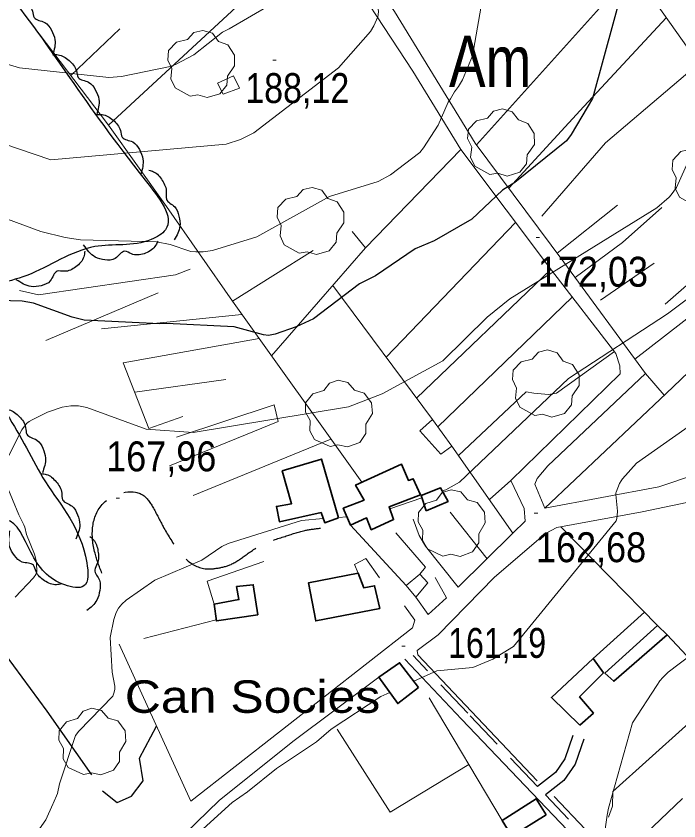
# Model space of a CAD drawing. Extents: x 480269 to 484877, y 4383588 to 4386804.
# Drawn here: x 480900.7 to 481094.5, y 4386070.7 to 4386306.1 of the extents above; entities that cross this region are included whole.
import ezdxf
from ezdxf.enums import TextEntityAlignment as Align

# ---------------------------------------------------------------- set-up
doc = ezdxf.new("R2010")
doc.units = 0
doc.header["$LTSCALE"] = 3.8
doc.linetypes.add('LONG_DASHED', pattern=[7.5, 6, -1.5])
doc.linetypes.add('MEDIUM_DASHED', pattern=[4.5, 3, -1.5])
for name, color, linetype, lineweight in [('25', 7, 'LONG_DASHED', 25), ('27', 7, 'Continuous', 25), ('29', 7, 'Continuous', 13), ('38', 7, 'Continuous', 25), ('47', 7, 'Continuous', 35), ('51', 7, 'Continuous', 13), ('7', 7, 'Continuous', 13), ('8', 7, 'Continuous', 25), ('9', 7, 'Continuous', 13)]:
    doc.layers.add(name, color=color, linetype=linetype, lineweight=lineweight)
doc.layers.add('31', color=7, linetype='Continuous')
doc.layers.add('5', color=7, linetype='Continuous')

msp = doc.modelspace()

# ---------------------------------------------------------------- linework, layer by layer
at = {"layer": '25'}
msp.add_lwpolyline([(480856.34, 4386178.85), (480880.34, 4386147.94), (480897.46, 4386119.43), (480909.61, 4386102.85), (480925.95, 4386079.55), (480930.22, 4386076.16), (480934.45, 4386078), (480937.79, 4386082.41), (480936.79, 4386089.08), (480941.75, 4386098.4)], dxfattribs=at)
at = {"layer": '27'}
for points in [[(480894.74, 4386365.82), (480903.52, 4386357.87), (480897.3, 4386347.37), (480895.04, 4386345.21), (480887.78, 4386337.47), (480888.64, 4386326.66), (480896.85, 4386314.59), (480916.25, 4386288.17), (480938.42, 4386258.12), (480944.36, 4386243.6), (480940.19, 4386240.76), (480923.67, 4386238.66), (480903.77, 4386230.25), (480885.41, 4386225.51), (480878.62, 4386222.15), (480876.15, 4386209.9), (480887.62, 4386200.28), (480897.9, 4386189.68), (480909.25, 4386169.92), (480921.33, 4386146.21), (480920.51, 4386139.43), (480914.92, 4386139.74), (480904.97, 4386149.33), (480897.67, 4386158.69), (480892.34, 4386157.19), (480887.81, 4386154.72)], [(480898.56, 4386312.26), (480900.11, 4386312.28), (480903.33, 4386310.6), (480905.44, 4386307.57), (480905.96, 4386305.65), (480909.02, 4386304.22), (480910.98, 4386301.97), (480912.02, 4386299.19), (480911.4, 4386294.76)], [(480911.39, 4386294.76), (480912.94, 4386294.78), (480916.16, 4386293.11), (480918.28, 4386290.08), (480918.81, 4386288.16), (480921.87, 4386286.74), (480923.83, 4386284.5), (480924.88, 4386281.72), (480924.26, 4386277.29)], [(480924.27, 4386277.29), (480925.82, 4386277.32), (480929.04, 4386275.64), (480931.16, 4386272.62), (480931.68, 4386270.7), (480934.75, 4386269.28), (480936.71, 4386267.04), (480937.76, 4386264.26), (480937.15, 4386259.83)], [(480939.46, 4386261.01), (480940.88, 4386260.57), (480943.41, 4386258.03), (480944.59, 4386254.53), (480944.6, 4386252.55), (480947.05, 4386250.3), (480948.28, 4386247.59), (480948.56, 4386244.64), (480946.91, 4386240.63)], [(480942.06, 4386240.24), (480941.23, 4386238.68), (480938.07, 4386236.6), (480934.38, 4386236.54), (480932.48, 4386237.32), (480929.61, 4386235.22), (480926.66, 4386234.78), (480923.76, 4386235.62), (480920.38, 4386239.24)], [(480920.76, 4386237.34), (480920.47, 4386235.68), (480918.15, 4386232.77), (480914.71, 4386231.45), (480912.68, 4386231.47), (480910.65, 4386228.65), (480908.02, 4386227.25), (480905.03, 4386226.99), (480900.73, 4386228.99)], [(480897.06, 4386191.06), (480898.58, 4386190.93), (480901.61, 4386188.96), (480903.45, 4386185.76), (480903.82, 4386183.8), (480906.72, 4386182.1), (480908.47, 4386179.69), (480909.28, 4386176.84), (480908.34, 4386172.52)], [(480907.99, 4386172.31), (480909.48, 4386172.08), (480912.36, 4386169.92), (480914.01, 4386166.62), (480914.27, 4386164.65), (480917.03, 4386162.76), (480918.63, 4386160.25), (480919.28, 4386157.36), (480918.11, 4386153.12)], [(480914.04, 4386140.06), (480912.47, 4386139.79), (480909, 4386140.96), (480906.49, 4386143.66), (480905.72, 4386145.51), (480902.44, 4386146.44), (480900.18, 4386148.38), (480898.78, 4386151.02), (480898.87, 4386155.58)], [(480922.2, 4386153.9), (480923.29, 4386152.96), (480924.61, 4386149.65), (480924.39, 4386145.96), (480923.67, 4386144.13), (480925.02, 4386141.11), (480925.13, 4386138.14), (480924.29, 4386135.31), (480921.36, 4386132.22)]]:
    msp.add_spline(points, degree=3, dxfattribs=at)
at = {"layer": '29'}
for points in [[(480951.52, 4386282.71), (480947.13, 4386285.14), (480945.91, 4386287.78), (480946.21, 4386290.74), (480945.01, 4386293.24), (480945.25, 4386295.98), (480947.58, 4386298.43), (480950.83, 4386299.2), (480952.63, 4386301.27), (480955.25, 4386301.92), (480958.06, 4386301.07), (480959.85, 4386298.67), (480962.6, 4386297.66), (480964.52, 4386294.67), (480964.54, 4386291.53), (480962.45, 4386288.51), (480962.26, 4386285.84), (480960.26, 4386283.36), (480956.56, 4386282.28), (480953.84, 4386283.1)], [(481039.19, 4386259.75), (481034.8, 4386262.18), (481033.58, 4386264.82), (481033.88, 4386267.78), (481032.68, 4386270.28), (481032.92, 4386273.02), (481035.25, 4386275.47), (481038.5, 4386276.24), (481040.3, 4386278.31), (481042.92, 4386278.96), (481045.73, 4386278.11), (481047.52, 4386275.71), (481050.27, 4386274.7), (481052.19, 4386271.71), (481052.21, 4386268.57), (481050.12, 4386265.55), (481049.93, 4386262.88), (481047.93, 4386260.4), (481044.23, 4386259.32), (481041.51, 4386260.14)], [(481099.01, 4386250.73), (481094.62, 4386253.16), (481093.4, 4386255.8), (481093.7, 4386258.76), (481092.5, 4386261.26), (481092.74, 4386264), (481095.07, 4386266.45), (481098.32, 4386267.22), (481100.12, 4386269.29), (481102.74, 4386269.94), (481105.55, 4386269.09), (481107.34, 4386266.69), (481110.09, 4386265.68), (481112.01, 4386262.69), (481112.03, 4386259.55), (481109.94, 4386256.53), (481109.75, 4386253.86), (481107.75, 4386251.38), (481104.05, 4386250.3), (481101.33, 4386251.12)], [(480983.48, 4386236.8), (480979.09, 4386239.23), (480977.87, 4386241.87), (480978.17, 4386244.83), (480976.97, 4386247.33), (480977.21, 4386250.07), (480979.54, 4386252.52), (480982.79, 4386253.29), (480984.59, 4386255.36), (480987.21, 4386256.01), (480990.02, 4386255.16), (480991.81, 4386252.76), (480994.56, 4386251.75), (480996.48, 4386248.76), (480996.5, 4386245.62), (480994.41, 4386242.6), (480994.22, 4386239.93), (480992.22, 4386237.45), (480988.52, 4386236.37), (480985.8, 4386237.19)], [(481052.3, 4386189.25), (481047.91, 4386191.68), (481046.69, 4386194.32), (481046.99, 4386197.28), (481045.79, 4386199.78), (481046.03, 4386202.52), (481048.36, 4386204.97), (481051.61, 4386205.74), (481053.41, 4386207.81), (481056.03, 4386208.46), (481058.84, 4386207.61), (481060.63, 4386205.21), (481063.38, 4386204.2), (481065.3, 4386201.21), (481065.32, 4386198.07), (481063.23, 4386195.05), (481063.04, 4386192.38), (481061.04, 4386189.9), (481057.34, 4386188.82), (481054.62, 4386189.64)], [(480992.46, 4386180.18), (480987.92, 4386182.3), (480986.51, 4386184.84), (480986.61, 4386187.82), (480985.24, 4386190.23), (480985.28, 4386192.98), (480987.44, 4386195.58), (480990.63, 4386196.58), (480992.28, 4386198.77), (480994.85, 4386199.6), (480997.71, 4386198.95), (480999.66, 4386196.68), (481002.47, 4386195.86), (481004.6, 4386193.01), (481004.84, 4386189.88), (481002.96, 4386186.73), (481002.96, 4386184.05), (481001.14, 4386181.44), (480997.52, 4386180.1), (480994.75, 4386180.73)], [(481025.46, 4386148.16), (481020.92, 4386150.28), (481019.51, 4386152.82), (481019.61, 4386155.8), (481018.24, 4386158.21), (481018.28, 4386160.96), (481020.44, 4386163.56), (481023.63, 4386164.56), (481025.28, 4386166.75), (481027.85, 4386167.58), (481030.71, 4386166.93), (481032.66, 4386164.66), (481035.47, 4386163.84), (481037.6, 4386160.99), (481037.84, 4386157.86), (481035.96, 4386154.71), (481035.96, 4386152.03), (481034.14, 4386149.42), (481030.52, 4386148.08), (481027.75, 4386148.71)], [(480920.42, 4386084.27), (480915.88, 4386086.39), (480914.47, 4386088.93), (480914.57, 4386091.91), (480913.2, 4386094.32), (480913.24, 4386097.07), (480915.4, 4386099.67), (480918.59, 4386100.67), (480920.24, 4386102.86), (480922.81, 4386103.69), (480925.67, 4386103.04), (480927.62, 4386100.77), (480930.43, 4386099.95), (480932.56, 4386097.1), (480932.8, 4386093.97), (480930.92, 4386090.82), (480930.92, 4386088.14), (480929.1, 4386085.53), (480925.48, 4386084.19), (480922.71, 4386084.82)]]:
    msp.add_lwpolyline(points, close=True, dxfattribs=at)
at = {"layer": '38', "linetype": 'MEDIUM_DASHED'}
for points in [[(481053.12, 4386080.83), (481032.72, 4386102.22), (481016.76, 4386119.13)], [(481066.69, 4386094.6), (481064.13, 4386087.3), (481060.86, 4386082.55), (481055.49, 4386078.34)], [(481156.34, 4385972.04), (481150.52, 4385977.39), (481115.59, 4386014.55), (481074.01, 4386058.91), (481055.49, 4386078.34)]]:
    msp.add_lwpolyline(points, dxfattribs=at)
at = {"layer": '38'}
for points in [[(481088.21, 4386040.09), (481072.19, 4386057.18), (481030.9, 4386100.49), (481014.36, 4386118.01)], [(481063.48, 4386095.73), (481061.07, 4386088.86), (481058.35, 4386084.92), (481053.12, 4386080.83)]]:
    msp.add_lwpolyline(points, dxfattribs=at)
at = {"layer": '38', "linetype": 'LONG_DASHED'}
msp.add_spline([(480925.74, 4386143.22), (480923.75, 4386148.99), (480923.09, 4386156.89), (480926.15, 4386163.57), (480937.58, 4386166.12), (480940.83, 4386162.18), (480943.66, 4386156.8), (480947.84, 4386150.18), (480950.02, 4386147.57), (480955.91, 4386144.47), (480958.92, 4386144.56), (480963.21, 4386145.62), (480967.62, 4386148.34), (480972.72, 4386151.55), (480979.31, 4386153.95), (480985.05, 4386155.65), (480989.68, 4386156.35)], degree=3, dxfattribs=at)
at = {"layer": '47', "lineweight": 13}
for points in [[(480965.96, 4386285.05), (480964.22, 4386288.57), (480959.53, 4386286.47), (480961.18, 4386283.25)], [(481028.1, 4386180.36), (481024.84, 4386177.98), (481018.69, 4386184.77), (481022.44, 4386188.07)], [(481017.55, 4386136.2), (481014.75, 4386139.6), (481018.73, 4386142.92), (481021.08, 4386140.31)]]:
    msp.add_lwpolyline(points, close=True, dxfattribs=at)
at = {"layer": '47'}
for points in [[(480994.96, 4386159.35), (480990.91, 4386157.9), (480989.82, 4386160.88), (480977.67, 4386158.23), (480976.76, 4386162.68), (480981.23, 4386163.5), (480978.5, 4386173.08), (480989.94, 4386176.54)], [(481018.88, 4386166.04), (481016.8, 4386170.81), (481015.4, 4386170.28), (481013.39, 4386175.01), (480999.95, 4386168.95), (481002.4, 4386164.53), (480996.33, 4386162.17), (480998.49, 4386157.25), (481003.11, 4386159.38), (481004.52, 4386155.9), (481011.02, 4386158.84), (481009.75, 4386162.54)], [(481020.6, 4386161.41), (481019.12, 4386165.85), (481024.72, 4386168.16), (481026.99, 4386164.16)], [(481007.05, 4386132.87), (481005.51, 4386139.48), (481002.31, 4386138.93), (481000.73, 4386143.14), (480986.21, 4386140.37), (480988.3, 4386129.23)], [(480971.35, 4386131.02), (480970, 4386139.78), (480965.13, 4386139.28), (480965.82, 4386135.48), (480958.59, 4386134.11), (480959.25, 4386129.24)], [(481090.99, 4386125.1), (481088.18, 4386127.9), (481072.82, 4386113.89), (481075.42, 4386111.58)], [(481018.35, 4386109.73), (481012.27, 4386105.03), (481006.75, 4386112.8), (481012.8, 4386116.99)], [(481065.47, 4386098.72), (481069.47, 4386102.26), (481065.41, 4386107.01), (481072.42, 4386114.08), (481069.36, 4386118.2), (481057.17, 4386106.84)], [(481055.69, 4386072.48), (481052.77, 4386077.21), (481042.75, 4386070.88), (481045.6, 4386066.28)]]:
    msp.add_lwpolyline(points, close=True, dxfattribs=at)
at = {"layer": '51'}
for p, q in [((481081.09, 4386319.45), (481035.25, 4386268.43)), ((480931.04, 4386302.37), (480916.63, 4386288.75)), ((481128.51, 4386255.16), (481090.48, 4386221.87)), ((481076.47, 4386250.75), (481058.87, 4386236.79)), ((481046.71, 4386245.72), (481008.84, 4386206.36)), ((480975.38, 4386206.69), (481002.81, 4386238.33)), ((481071.59, 4386223.01), (481087.28, 4386233.88)), ((481057.05, 4386231.95), (481017.77, 4386194.35)), ((480942.23, 4386225.15), (480909.38, 4386211.23)), ((480993.25, 4386227.31), (481022.44, 4386188.07)), ((481108.66, 4386226.86), (481081.61, 4386205.79)), ((480963.98, 4386222.68), (481001.71, 4386169.75)), ((481023.98, 4386185.98), (481063.24, 4386223.94)), ((480966.71, 4386218.86), (480925.68, 4386214.63)), ((481084.66, 4386201.61), (481090.21, 4386195.21)), ((480935.37, 4386196.09), (480962.04, 4386199.81)), ((480992.71, 4386182.39), (480952.41, 4386165.87)), ((481039.04, 4386164.74), (481045.34, 4386170.29)), ((481038.39, 4386147.42), (481027.63, 4386161.01)), ((481014.75, 4386139.6), (480998.49, 4386157.25)), ((481088.18, 4386127.9), (481059.9, 4386156.73)), ((481084.41, 4386131.75), (481069.36, 4386118.2)), ((480959.21, 4386129.57), (480938.04, 4386124.03)), ((481042.75, 4386070.88), (481021.45, 4386106.7))]:
    msp.add_line(p, q, dxfattribs=at)
for points in [[(480958.77, 4386370.61), (480967.17, 4386363.32), (480968.05, 4386358.24), (480986.91, 4386329.03), (480927.67, 4386274.19), (480879.06, 4386338.23), (480954.14, 4386381.93), (480897.09, 4386455.73)], [(481055.25, 4386162.19), (481052.34, 4386169.16), (481052.98, 4386170.88), (481056.1, 4386174.57), (481084.66, 4386201.61), (481060.82, 4386234.17), (481034.86, 4386268.94), (481011.35, 4386307.44), (480993.89, 4386332.55), (480974.1, 4386361.86), (480962.78, 4386374.12), (480957.61, 4386383.95), (481005.55, 4386413.98), (481080.84, 4386319.8), (481109.74, 4386278.85)], [(480993.42, 4386325.52), (481016.67, 4386289.98), (481030.67, 4386267.08), (481002.81, 4386238.33), (480998.91, 4386243.06)], [(481044.74, 4386255.72), (481066.69, 4386279.64), (481090.82, 4386305.67)], [(481054.37, 4386247.6), (481073.02, 4386269.07), (481100.28, 4386292.27)], [(480987.54, 4386237.5), (480963.98, 4386222.68), (480944.64, 4386250.37), (480927.67, 4386274.19)], [(481028.1, 4386180.36), (481045.95, 4386154.86), (481049.54, 4386158.39), (481049.26, 4386162.14), (481045.34, 4386170.29), (481077.25, 4386201.44), (481077.24, 4386203.79), (481076.02, 4386207.41), (481057.19, 4386231.75), (481030.67, 4386267.08)], [(481189.43, 4386238.35), (481184.8, 4386233.8), (481167.77, 4386215.52), (481149.6, 4386199.89), (481132.43, 4386187.68), (481111.54, 4386176.08), (481088.62, 4386168.47), (481055.25, 4386162.19), (481090.79, 4386195.75), (481138.64, 4386241.42), (481164.71, 4386260.99), (481179.45, 4386241.02)], [(481089.46, 4386250.08), (481077.96, 4386239.88), (481064.12, 4386229.67)], [(480951.53, 4386232.06), (480947.3, 4386230.43), (480907.22, 4386224.57), (480901.69, 4386225.86)], [(480949.42, 4386188.96), (480939.51, 4386185.51), (480931.99, 4386204.66), (480971.71, 4386211.84)], [(481075.61, 4386207.96), (481058.71, 4386195.85), (481056.34, 4386195.4), (481052.06, 4386195.78), (481049.81, 4386196.23), (481030.02, 4386177.63)], [(480945.54, 4386174.57), (480977.3, 4386187.55), (480976.14, 4386192.43), (480947.53, 4386182.97)], [(481137.19, 4386181.91), (481117.19, 4386171.32), (481105.67, 4386165.67), (481083.75, 4386161.16), (481058.74, 4386156.51), (481055.51, 4386154.8), (481040.51, 4386142.05), (481024.04, 4386125.12), (481017.98, 4386120.55), (481018.16, 4386119.27), (481053.02, 4386082.5)], [(481045.95, 4386154.86), (481029.9, 4386139.06), (481020.33, 4386151.05), (481018.51, 4386154.21), (481016.73, 4386159.01)], [(481018.73, 4386142.92), (481020.38, 4386144.92), (481011.69, 4386155.02)], [(481000.73, 4386143.14), (480999.63, 4386145.67), (481002.95, 4386147.51), (481006.94, 4386141.78)], [(480973.14, 4386146.59), (480956.54, 4386140.89), (480958.59, 4386134.11)], [(481017.55, 4386136.2), (481021.12, 4386131.05), (481026.5, 4386135.93), (481023.16, 4386141.96)], [(480930.79, 4386122.46), (480951.71, 4386076.52), (481016.56, 4386127.19), (481017.25, 4386129.43), (481014.25, 4386133.58)], [(481103.13, 4386083.72), (481116.69, 4386097.73), (481090.99, 4386125.1)], [(481006.75, 4386112.8), (480981.6, 4386093.97), (480960.08, 4386076.69), (480936.94, 4386054.31)], [(481073.85, 4386071.81), (481075.02, 4386075.02), (481075.2, 4386079.34), (481107.07, 4386107.99)], [(481033.02, 4386087.26), (481010.07, 4386073.25), (480994.52, 4386097.54)], [(481058.01, 4386077.88), (481076.11, 4386058.8), (481095.51, 4386077.3)]]:
    msp.add_lwpolyline(points, dxfattribs=at)
at = {"layer": '7'}
for p, q in [((480975.73, 4386293.2), (480976.73, 4386293.2)), ((481052.73, 4386241.32), (481053.73, 4386241.32)), ((480929.89, 4386165.07), (480930.89, 4386165.07)), ((481052.18, 4386160.76), (481053.18, 4386160.76)), ((481013.47, 4386121.87), (481014.47, 4386121.87))]:
    msp.add_line(p, q, dxfattribs=at)
at = {"layer": '8'}
msp.add_lwpolyline([(481078.54, 4386316.34), (481069.24, 4386282), (481063, 4386271.42), (481061.64, 4386269.61), (481046.46, 4386257.47), (481042.87, 4386255.17), (481033.95, 4386246.73), (481022.95, 4386240.35), (481017.31, 4386238.05), (481005.74, 4386230.13), (481001.08, 4386227.79), (480987.6, 4386217.57), (480982.57, 4386215.22), (480976.42, 4386213.04), (480974.47, 4386212.72), (480973.04, 4386212.86), (480964.45, 4386215.17), (480944.69, 4386216.21), (480942.71, 4386216.05), (480920.56, 4386217.17), (480917.02, 4386218), (480905.8, 4386222.18), (480902.4, 4386222.77), (480881.9, 4386223.26)], dxfattribs=at)
at = {"layer": '9'}
for p, q in [((481009.94, 4386161.97), (481019.34, 4386165.19)), ((480994.92, 4386159.49), (480997.42, 4386159.69))]:
    msp.add_line(p, q, dxfattribs=at)
for points in [[(480954.05, 4386455.59), (480977.48, 4386415), (480997.2, 4386366.97), (481000.56, 4386360.63), (481006.24, 4386342.52), (481006.69, 4386340.18), (481006.15, 4386324.5), (481004.84, 4386314.8), (481004.95, 4386313.81), (481006.47, 4386308.52), (481006.62, 4386307.52), (481006.57, 4386306.47), (481006.46, 4386305.91), (481005.3, 4386303.23), (481004.26, 4386301.62), (480994.92, 4386290.95), (480970.14, 4386271.94), (480966.31, 4386270.03), (480962.1, 4386268.63), (480910.85, 4386264.1), (480892.11, 4386270.37)], [(481025.25, 4386167.22), (481026.34, 4386167.59), (481030.34, 4386169.8), (481062.15, 4386200.1), (481091.1, 4386219.01), (481113.42, 4386235.76), (481118.59, 4386241.2), (481125.31, 4386251.51), (481125.84, 4386252.95), (481126.17, 4386254.79), (481126.47, 4386261.82), (481119.29, 4386309.93), (481120.76, 4386359.37), (481119.92, 4386362.24), (481112.34, 4386380.2), (481073.31, 4386443.98), (481068.88, 4386455.32)], [(481038.01, 4386316.84), (481034.12, 4386294.5), (481031.23, 4386287.45), (481030.05, 4386285.52), (481028.87, 4386283.91), (481027.73, 4386281.88), (481027.08, 4386281.06), (481026.97, 4386280.95), (481024.08, 4386274.22), (481019.78, 4386267.59), (481018.67, 4386266.21), (481010.15, 4386259.69), (481006.49, 4386257.72), (480992.26, 4386253.36), (480971.06, 4386241.56), (480958.12, 4386237.57), (480955.33, 4386237.13), (480953.25, 4386237.1), (480951.64, 4386237.29), (480951.48, 4386237.32), (480945.71, 4386239.31), (480941.73, 4386240.11), (480919.54, 4386240.68), (480914.98, 4386241.3), (480907.85, 4386243.05), (480898.16, 4386246.69)], [(480865.21, 4386301.74), (480901.63, 4386290.91), (480927.75, 4386288.11), (480931.44, 4386288.41), (480945.67, 4386291.3), (480947.29, 4386291.96), (480952.63, 4386294.8), (480961.03, 4386301.38), (480961.6, 4386301.72), (480962.96, 4386302.34), (480974.83, 4386309.27)], [(480898.51, 4386177.57), (480902.3, 4386185.12), (480903.71, 4386186.91), (480904.46, 4386187.51), (480905.32, 4386188.05), (480909.85, 4386190.23), (480914.12, 4386191.7), (480916.71, 4386192.14), (480918.88, 4386192.08), (480921.32, 4386191.59), (480938.71, 4386185.33), (480952.45, 4386184.36), (480997.84, 4386191.82), (481007.67, 4386195.6), (481025.4, 4386205.25), (481038.36, 4386218.01), (481045, 4386223.36), (481088, 4386249.99), (481091.63, 4386253.09), (481092.22, 4386253.77), (481093.73, 4386255.97), (481098.82, 4386267.25)], [(481016.95, 4386111.57), (481023.66, 4386114.66), (481034.24, 4386115.6), (481040.07, 4386118.01), (481046.08, 4386121.72), (481076.1, 4386158.51), (481076.3, 4386159.14), (481076.46, 4386160), (481076.49, 4386161.33), (481076.01, 4386166.16), (481076.07, 4386166.7), (481076.12, 4386166.87), (481077.14, 4386169.43), (481077.54, 4386170.18), (481077.97, 4386170.79), (481082.1, 4386175.35), (481128.74, 4386208.16)], [(480900.42, 4386136.18), (480905.8, 4386141.84), (480906.45, 4386142.81), (480906.71, 4386143.67), (480906.77, 4386144.21), (480906.53, 4386146.89), (480906.05, 4386148.72), (480903.75, 4386154.45), (480903.22, 4386156.62), (480902.96, 4386157.29), (480901.42, 4386160.28), (480897.77, 4386169.22)], [(480905.44, 4386065.45), (480909.37, 4386071.03), (480911.4, 4386075.59), (480911.55, 4386075.85), (480912.75, 4386078.7), (480913.36, 4386081.6), (480918.04, 4386095.69), (480918.98, 4386096.95), (480928.95, 4386107.17), (480929.36, 4386108.34), (480929.52, 4386109.3), (480929.49, 4386110.14), (480928.74, 4386114.21), (480928.2, 4386124.35), (480928.21, 4386124.36), (480929.27, 4386129.62), (480929.95, 4386131.72), (480930.65, 4386132.94), (480931.59, 4386134.08), (480932.88, 4386135.25), (480941.28, 4386141.15), (480954.99, 4386146.95), (480960.85, 4386150.94), (480962.64, 4386151.82), (480984.14, 4386158.61), (480990.46, 4386159.13)], [(481072.87, 4386068.33), (481073.53, 4386072.38), (481073.88, 4386074.44), (481080.92, 4386099.39), (481087.97, 4386110.36), (481088.92, 4386111.73), (481089.73, 4386112.68), (481091.3, 4386114.2), (481108.23, 4386126.96)], [(480891.51, 4386017.56), (480919.82, 4386043.88), (480927.71, 4386049.33), (480929.35, 4386049.9), (480934.54, 4386050.38), (480935.39, 4386050.74), (480935.68, 4386050.91), (480937.33, 4386052.08), (480963.81, 4386076.16), (480968.36, 4386079.23), (480976.85, 4386086.07), (480988.54, 4386093.88), (480992.8, 4386097.53), (481007.31, 4386107.12), (481009.93, 4386108.33)]]:
    msp.add_lwpolyline(points, dxfattribs=at)

# ---------------------------------------------------------------- texts
at = {"layer": '31', "width": 0.8}
msp.add_text('Am', height=15, dxfattribs=at).set_placement((481039.28, 4386285.36), align=Align.CENTER)
at = {"layer": '5', "width": 1.15}
msp.add_text('Can Socies', height=9.5, dxfattribs=at).set_placement((481007.16, 4386102.34), align=Align.RIGHT)
at = {"layer": '7'}
for s, width, p in [('188,12', 0.85, (480967.67, 4386280.66)), ('172,03', 0.9, (481053.23, 4386226.95)), ('167,96', 0.9, (480927, 4386172.97)), ('162,68', 0.9, (481052.68, 4386146.39)), ('161,19', 0.8, (481027.01, 4386118.41))]:
    msp.add_text(s, height=8.75, dxfattribs=dict(at, width=width)).set_placement(p)

doc.saveas('drawing.dxf')
